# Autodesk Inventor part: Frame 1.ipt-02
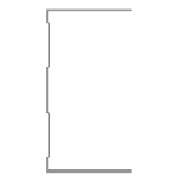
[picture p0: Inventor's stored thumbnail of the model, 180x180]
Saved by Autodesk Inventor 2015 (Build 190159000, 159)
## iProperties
IsCustomPart: 1
Created: 2015-04
Part Number: Frame 1.ipt-02
Material: Aluminum 6061
Description: Kévin Novo
Document SubType Name: Modeling
Standard: Kevin
Designer: suporte
Standards Organization: Kevin
Language: en-US
Size Designation: (Unnamed 2)
Categories: <MemberInstance><Categories><Category DisplayName="Structural Shapes" InternalName="089c4875-fa83-4c05-b084-43b9cc11f5ed" Mnemonic="GRDR"><CategoryParameter Dis
Density: 2.7 g/cm^3
Appearance: Aluminum - Flat
_CCFamilyMember: 2
_CCFamilyDisplayName: Kévin - Kévin Novo
_FrameMemberDoc: Frame Member File
_Version: 15.0.0
_GetPNFromCC: 1
G_W: 50,000 mm
G_H: 75,000 mm
G_L: 2100,000 mm
+396E3247-1B50-4529-8CC2-DA6BE49CE099+CUTDETAIL1: Notch
Author: suporte
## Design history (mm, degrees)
node "Start Plane"
node "End Plane"
sketch "Sketch"
  geometry: L1 (24.7, 37.5)-(24.7, 36.9); L2 (24.7, 36.9)-(-24.7, 36.9); L3 (-24.7, -36.9)-(24.7, -36.9); L4 (24.7, -36.9)-(24.7, -37.5); L5 (24.7, -37.5)-(-25.3, -37.5); L6 (-25.3, 37.5)-(24.7, 37.5); L7 (-24.7, 36.9)-(-24.7, 31.9); L8 (-24.7, 31.9)-(-23.3, 30.5); L9 (-23.3, 30.5)-(-23.3, 10.934); L10 (-23.3, 10.934)-(-24.7, 9.534); L11 (-24.7, 9.534)-(-24.7, -9.534); L12 (-24.7, -9.534)-(-23.3, -10.934); L13 (-23.3, -10.934)-(-23.3, -30.5); L14 (-23.3, -30.5)-(-24.7, -31.9); L15 (-24.7, -31.9)-(-24.7, -36.9); L16 (-25.3, -37.5)-(-25.3, -31.651); L17 (-25.3, -31.651)-(-23.9, -30.251); L18 (-23.9, -30.251)-(-23.9, -11.183); L19 (-23.9, -11.183)-(-25.3, -9.783); L20 (-25.3, -9.783)-(-25.3, 9.783); L21 (-25.3, 9.783)-(-23.9, 11.183); L22 (-23.9, 11.183)-(-23.9, 30.251); L23 (-23.9, 30.251)-(-25.3, 31.651); L24 (-25.3, 31.651)-(-25.3, 37.5); L25 (-25.3, 0)-(30.37, 0); 3 further points
  constraints: 50 end point, 10 point on line, 9 parallel, 5 perpendicular, 4 equal length, 3 midpoint, 3 vertical, 2 vertical alignment, 1 collinear, 1 horizontal, 1 horizontal alignment
  dimensions: "d3" = 0.6 distance of L1.start L1.end (= d6); "d5" = 75 distance between parallel lines of L5 L6; "d6" = 0.6 distance between parallel lines of L24 L7 (= d8); "d7" = 0.6 distance between parallel lines of L8 L23 (= d8); "d8" = 0.6 distance between parallel lines of L22 L9 (= d12); "Espessura" = 0.6 distance between parallel lines of L17 L14; "d10" = 0.6 distance between parallel lines of L13 L18 (= Espessura); "d11" = 0.6 distance between parallel lines of L12 L19 (= Espessura); "d12" = 0.6 distance between parallel lines of L21 L10 (= d11); "d13" = 5 distance of L2.end L7.end; "d15" = 135 deg angle of L9 L8; "d16" = 2 distance between parallel lines of L24 L9; "d17" = 50 distance of L6.start L1.start
extrude "Body" join sketch "Sketch" stored distance "d24" = 0.13; taper "d25" = 0 deg
node "Driven Length"
  sketch "Sketch10"
    geometry: L1 (0, 0)-(10, 0) reference
    constraints: 2 end point, 1 horizontal
  workplane "Work Plane7"
  sketch "Sketch11"
    geometry: L1 (-2, 0)-(12, 0) reference; L2 (-2, 2100)-(12, 2100) reference
    dimensions: "d27" = 2100 distance between parallel lines of L1 L2 (derived)
workplane "Work Plane8"
workplane "Work Plane9"
workplane "Work Plane10"
sketch "Sketch12"
  geometry: L1 (24.7, 37.5)-(24.7, 36.9); L2 (24.7, 36.9)-(-24.7, 36.9); L3 (-24.7, 36.9)-(-24.7, 31.9); L4 (-24.7, 31.9)-(-23.3, 30.5); L5 (-23.3, 30.5)-(-23.3, 10.934); L6 (-23.3, 10.934)-(-24.7, 9.534); L7 (-24.7, 9.534)-(-24.7, -9.534); L8 (-24.7, -9.534)-(-23.3, -10.934); L9 (-23.3, -10.934)-(-23.3, -30.5); L10 (-23.3, -30.5)-(-24.7, -31.9); L11 (-24.7, -31.9)-(-24.7, -36.9); L12 (-24.7, -36.9)-(24.7, -36.9); L13 (24.7, -36.9)-(24.7, -37.5); L14 (24.7, -37.5)-(-25.3, -37.5); L15 (-25.3, -37.5)-(-25.3, -31.651); L16 (-25.3, -31.651)-(-23.9, -30.251); L17 (-23.9, -30.251)-(-23.9, -11.183); L18 (-23.9, -11.183)-(-25.3, -9.783); L19 (-25.3, -9.783)-(-25.3, 9.783); L20 (-25.3, 9.783)-(-23.9, 11.183); L21 (-23.9, 11.183)-(-23.9, 30.251); L22 (-23.9, 30.251)-(-25.3, 31.651); L23 (-25.3, 31.651)-(-25.3, 37.5); L24 (-25.3, 37.5)-(24.7, 37.5)
  constraints: 48 end point, 10 point on line
extrude "Extrusion3" cut sketch "Sketch12" stored distance "d36" = 0.13; taper "d37" = 0 deg
body "Solid1"
other parameters: "G_OFFSET_START" = 0 [user parameter; used in 1 equation term], "G_OFFSET_END" = 0 [user parameter; used in 1 equation term], "d22" = 0 (computed from G_OFFSET_START), "G_L" = 2100 (= d27) [user parameter], "d34" = 90 deg
